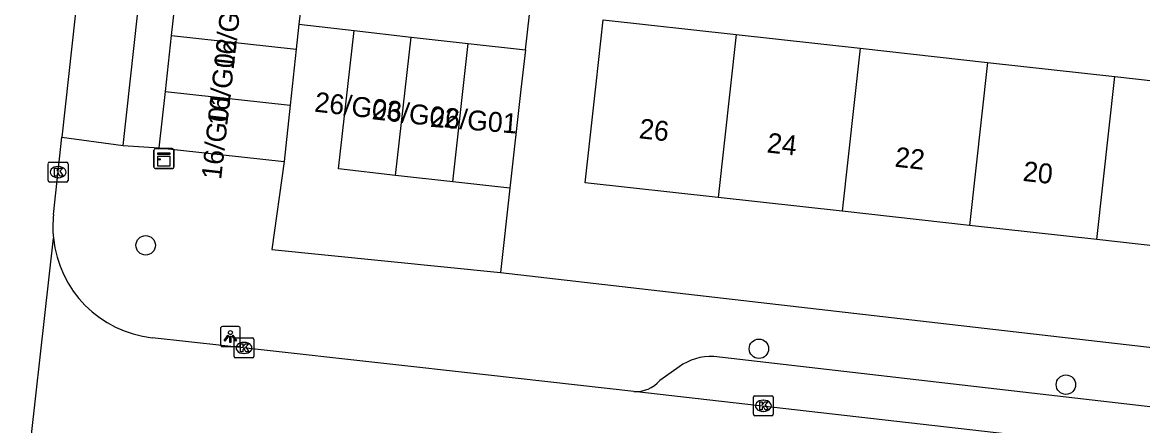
# Model space of a CAD drawing. Extents: x 161928 to 163055, y 386475 to 387428.
# Drawn here: x 162178.5 to 162234.9, y 387044.1 to 387064.4 of the extents above; entities that cross this region are included whole.
import ezdxf

# ---------------------------------------------------------------- set-up
doc = ezdxf.new("R2010")
doc.units = 0
for name, color, linetype in [('IMGEO_Boom', 7, 'Continuous'), ('IMGEO_Kast', 7, 'Continuous'), ('IMGEO_Kolk', 7, 'Continuous'), ('IMGEO_Lichtpunt', 7, 'Continuous'), ('IMGEO_Pand', 7, 'Continuous'), ('IMGEO_Pand_nummerreeks', 7, 'Continuous'), ('IMGEO_Rijbaan_lokaal_open', 7, 'Continuous'), ('IMGEO_Voetpad_open', 7, 'Continuous')]:
    doc.layers.add(name, color=color, linetype=linetype)

msp = doc.modelspace()

# ---------------------------------------------------------------- linework, layer by layer
at = {"layer": 'IMGEO_Boom'}
for centre in [(162184.742, 387053.165), (162215.596, 387047.966), (162231.042, 387046.162)]:
    msp.add_circle(centre, 0.489, dxfattribs=at)
at = {"layer": 'IMGEO_Kast'}
for p, q in [((162185.234, 387058.024), (162186.075, 387058.024)), ((162186.075, 387058.024), (162185.234, 387058.024)), ((162186.159, 387057.949), (162186.159, 387057.108)), ((162186.159, 387057.108), (162186.159, 387057.949)), ((162185.159, 387057.099), (162185.159, 387057.94)), ((162185.159, 387057.94), (162185.159, 387057.099)), ((162186.084, 387057.024), (162185.243, 387057.024)), ((162185.243, 387057.024), (162186.084, 387057.024))]:
    msp.add_line(p, q, dxfattribs=at)
for points in [[(162185.354, 387057.814), (162185.954, 387057.814), (162185.954, 387057.729), (162185.354, 387057.729), (162185.354, 387057.814)], [(162185.354, 387057.639), (162185.954, 387057.639), (162185.954, 387057.15), (162185.354, 387057.15), (162185.354, 387057.639)]]:
    msp.add_lwpolyline(points, dxfattribs=at)
msp.add_circle((162185.438, 387057.488), 0.0377, dxfattribs=at)
for centre, start, end in [((162185.237, 387057.946), 92.4484, 184.2845), ((162185.237, 387057.946), 92.4484, 184.2845), ((162186.081, 387057.946), 2.4484, 94.2845), ((162186.081, 387057.946), 2.4484, 94.2845), ((162185.237, 387057.102), 182.4484, 274.2845), ((162185.237, 387057.102), 182.4484, 274.2845), ((162186.081, 387057.102), 272.4484, 4.2845), ((162186.081, 387057.102), 272.4484, 4.2845)]:
    msp.add_arc(centre, 0.0779, start, end, dxfattribs=at)
at = {"layer": 'IMGEO_Kolk'}
for p, q in [((162179.837, 387056.416), (162179.837, 387057.268)), ((162179.912, 387057.342), (162180.764, 387057.342)), ((162180.325, 387057.122), (162180.35, 387057.122)), ((162180.838, 387057.268), (162180.838, 387056.416)), ((162180.764, 387056.342), (162179.912, 387056.342)), ((162180.348, 387056.562), (162180.323, 387056.562)), ((162189.187, 387047.583), (162189.187, 387048.435)), ((162189.262, 387048.509), (162190.114, 387048.509)), ((162190.188, 387048.435), (162190.188, 387047.583)), ((162189.675, 387048.289), (162189.7, 387048.289)), ((162190.114, 387047.509), (162189.262, 387047.509)), ((162189.698, 387047.729), (162189.673, 387047.729)), ((162215.394, 387045.601), (162216.246, 387045.601)), ((162215.319, 387044.675), (162215.319, 387045.527)), ((162215.807, 387045.381), (162215.832, 387045.381)), ((162216.32, 387045.527), (162216.32, 387044.675)), ((162216.246, 387044.601), (162215.394, 387044.601)), ((162215.83, 387044.821), (162215.805, 387044.821))]:
    msp.add_line(p, q, dxfattribs=at)
for points in [[(162179.837, 387056.416), (162179.837, 387057.268)], [(162179.912, 387057.342), (162180.764, 387057.342)], [(162180.158, 387057.042), (162180.281, 387057.042), (162180.281, 387056.891), (162180.411, 387057.042), (162180.575, 387057.042), (162180.429, 387056.891), (162180.582, 387056.642), (162180.43, 387056.642), (162180.345, 387056.806), (162180.281, 387056.739), (162180.281, 387056.642), (162180.158, 387056.642), (162180.158, 387057.042)], [(162180.838, 387057.268), (162180.838, 387056.416)], [(162180.764, 387056.342), (162179.912, 387056.342)], [(162189.187, 387047.583), (162189.187, 387048.435)], [(162189.262, 387048.509), (162190.114, 387048.509)], [(162190.188, 387048.435), (162190.188, 387047.583)], [(162189.508, 387048.209), (162189.631, 387048.209), (162189.631, 387048.058), (162189.761, 387048.209), (162189.925, 387048.209), (162189.779, 387048.058), (162189.932, 387047.809), (162189.78, 387047.809), (162189.695, 387047.973), (162189.631, 387047.906), (162189.631, 387047.809), (162189.508, 387047.809), (162189.508, 387048.209)], [(162190.114, 387047.509), (162189.262, 387047.509)], [(162215.394, 387045.601), (162216.246, 387045.601)], [(162215.319, 387044.675), (162215.319, 387045.527)], [(162215.64, 387045.301), (162215.763, 387045.301), (162215.763, 387045.15), (162215.893, 387045.301), (162216.057, 387045.301), (162215.911, 387045.15), (162216.064, 387044.901), (162215.912, 387044.901), (162215.827, 387045.065), (162215.763, 387044.998), (162215.763, 387044.901), (162215.64, 387044.901), (162215.64, 387045.301)], [(162216.32, 387045.527), (162216.32, 387044.675)], [(162216.246, 387044.601), (162215.394, 387044.601)]]:
    msp.add_lwpolyline(points, dxfattribs=at)
for centre, start, end in [((162179.914, 387057.266), 91.552, 178.448), ((162179.914, 387057.266), 91.552, 178.448), ((162180.762, 387057.266), 1.552, 88.448), ((162180.762, 387057.266), 1.552, 88.448), ((162179.914, 387056.418), 181.552, 268.448), ((162179.914, 387056.418), 181.552, 268.448), ((162180.762, 387056.418), 271.552, 358.448), ((162180.762, 387056.418), 271.552, 358.448), ((162189.264, 387048.433), 91.552, 178.448), ((162189.264, 387048.433), 91.552, 178.448), ((162190.112, 387048.433), 1.552, 88.448), ((162190.112, 387048.433), 1.552, 88.448), ((162189.264, 387047.585), 181.552, 268.448), ((162189.264, 387047.585), 181.552, 268.448), ((162190.112, 387047.585), 271.552, 358.448), ((162190.112, 387047.585), 271.552, 358.448), ((162215.396, 387045.525), 91.552, 178.448), ((162215.396, 387045.525), 91.552, 178.448), ((162216.244, 387045.525), 1.552, 88.448), ((162216.244, 387045.525), 1.552, 88.448), ((162215.396, 387044.677), 181.552, 268.448), ((162215.396, 387044.677), 181.552, 268.448), ((162216.244, 387044.677), 271.552, 358.448), ((162216.244, 387044.677), 271.552, 358.448)]:
    msp.add_arc(centre, 0.0765, start, end, dxfattribs=at)
for centre, major_axis, ratio, start_param, end_param in [((162180.324, 387056.842), (-0.387, 0.002), 0.722429, 4.712389, 7.853982), ((162180.349, 387056.842), (-0.39, 0.002), 0.717154, 1.570796, 4.712389), ((162189.674, 387048.009), (-0.387, 0.002), 0.722429, 4.712389, 7.853982), ((162189.699, 387048.009), (-0.39, 0.002), 0.717154, 1.570796, 4.712389), ((162215.806, 387045.101), (-0.387, 0.002), 0.722429, 4.712389, 7.853982), ((162215.831, 387045.101), (-0.39, 0.002), 0.717154, 1.570796, 4.712389)]:
    msp.add_ellipse(centre, major_axis=major_axis, ratio=ratio, start_param=start_param, end_param=end_param, dxfattribs=at)
at = {"layer": 'IMGEO_Lichtpunt'}
for p, q in [((162188.506, 387048.982), (162188.506, 387048.175)), ((162188.506, 387048.982), (162188.506, 387048.175)), ((162189.408, 387049.077), (162188.6, 387049.077)), ((162189.408, 387049.077), (162188.6, 387049.077)), ((162189.502, 387048.175), (162189.502, 387048.982)), ((162189.502, 387048.175), (162189.502, 387048.982)), ((162188.6, 387048.081), (162189.408, 387048.081)), ((162188.6, 387048.081), (162189.408, 387048.081))]:
    msp.add_line(p, q, dxfattribs=at)
for points in [[(162188.88, 387048.646), (162188.919, 387048.618), (162188.731, 387048.356), (162188.693, 387048.383), (162188.88, 387048.646)], [(162188.982, 387048.598), (162189.029, 387048.598), (162189.029, 387048.276), (162188.982, 387048.276), (162188.982, 387048.598)], [(162189.092, 387048.618), (162189.13, 387048.645), (162189.317, 387048.383), (162189.278, 387048.355), (162189.092, 387048.618)]]:
    msp.add_lwpolyline(points, dxfattribs=at)
msp.add_circle((162189.005, 387048.78), 0.0994, dxfattribs=at)
for centre, start, end in [((162188.6, 387048.982), 90, 180), ((162188.6, 387048.982), 90, 180), ((162189.408, 387048.982), 0, 90), ((162189.408, 387048.982), 0, 90), ((162188.6, 387048.175), 180, 270), ((162188.6, 387048.175), 180, 270), ((162189.408, 387048.175), 270, 0), ((162189.408, 387048.175), 270, 360)]:
    msp.add_arc(centre, 0.0946, start, end, dxfattribs=at)
at = {"layer": 'IMGEO_Pand'}
for points in [[(162203.848, 387062.981), (162205.287, 387075.728)], [(162186.043, 387063.707), (162186.351, 387066.527)], [(162192.624, 387065.842), (162192.452, 387064.271)], [(162192.452, 387064.271), (162192.316, 387063.022)], [(162192.452, 387064.271), (162195.226, 387063.957)], [(162213.546, 387055.569), (162206.856, 387056.312), (162207.408, 387061.282), (162207.765, 387064.503), (162214.456, 387063.76)], [(162185.735, 387060.888), (162186.043, 387063.707)], [(162186.043, 387063.707), (162192.316, 387063.022)], [(162197.315, 387056.68), (162194.441, 387057.004), (162195.226, 387063.957)], [(162195.226, 387063.957), (162198.1, 387063.632)], [(162197.315, 387056.68), (162198.1, 387063.632)], [(162198.1, 387063.632), (162200.973, 387063.306)], [(162214.456, 387063.76), (162213.546, 387055.569)], [(162214.456, 387063.76), (162220.693, 387063.068)], [(162192.316, 387063.022), (162192.008, 387060.202)], [(162200.189, 387056.355), (162200.973, 387063.306)], [(162200.973, 387063.306), (162203.848, 387062.981)], [(162220.693, 387063.068), (162219.784, 387054.877)], [(162220.693, 387063.068), (162227.101, 387062.356)], [(162203.848, 387062.981), (162203.624, 387061), (162203.063, 387056.031)], [(162227.101, 387062.356), (162226.191, 387054.165)], [(162227.101, 387062.356), (162233.511, 387061.644)], [(162232.602, 387053.453), (162233.511, 387061.644)], [(162233.511, 387061.644), (162239.898, 387060.935)], [(162185.427, 387058.068), (162185.735, 387060.888)], [(162185.735, 387060.888), (162192.008, 387060.202)], [(162192.008, 387060.202), (162191.701, 387057.384)], [(162185.427, 387058.068), (162191.701, 387057.384)], [(162200.189, 387056.355), (162197.315, 387056.68)], [(162203.063, 387056.031), (162200.189, 387056.355)], [(162219.784, 387054.877), (162213.546, 387055.569)], [(162226.191, 387054.165), (162219.784, 387054.877)], [(162232.602, 387053.453), (162226.191, 387054.165)], [(162238.988, 387052.744), (162232.602, 387053.453)]]:
    msp.add_lwpolyline(points, dxfattribs=at)
at = {"layer": 'IMGEO_Rijbaan_lokaal_open'}
for points in [[(162181.783, 387083.862), (162181.799, 387083.827), (162182.152, 387082.946), (162182.426, 387082.038), (162182.617, 387081.108), (162182.724, 387080.165), (162182.686, 387078.275), (162180.528, 387058.594)], [(162180.103, 387054.713), (162180.528, 387058.594)], [(162178.539, 387039.621), (162180.099, 387053.527)], [(162209.297, 387045.816), (162201.982, 387046.634), (162190.553, 387047.911), (162185.07, 387048.523)], [(162292.807, 387036.295), (162209.297, 387045.816)]]:
    msp.add_lwpolyline(points, dxfattribs=at)
for centre, radius, start, end in [((162185.757, 387054.101), 5.687, 173.8218, 185.7917), ((162185.682, 387054.102), 5.613, 185.883, 263.7379)]:
    msp.add_arc(centre, radius, start, end, dxfattribs=at)
at = {"layer": 'IMGEO_Voetpad_open'}
for points in [[(162183.617, 387058.182), (162185.796, 387078.002)], [(162180.528, 387058.594), (162183.617, 387058.182)], [(162183.617, 387058.182), (162185.427, 387058.068)], [(162191.701, 387057.384), (162191.095, 387052.958), (162202.596, 387051.794)], [(162203.063, 387056.031), (162202.596, 387051.794)], [(162202.596, 387051.794), (162288.423, 387041.928), (162292.928, 387041.432)], [(162289.168, 387038.822), (162288.165, 387038.944), (162213.325, 387047.577)], [(162211.581, 387047.056), (162210.611, 387046.365)]]:
    msp.add_lwpolyline(points, dxfattribs=at)
for centre, radius, start, end in [((162213.18, 387044.882), 2.699, 86.9298, 126.3361), ((162209.39, 387047.44), 1.627, 266.723, 318.6281)]:
    msp.add_arc(centre, radius, start, end, dxfattribs=at)

# ---------------------------------------------------------------- texts
at = {"layer": 'IMGEO_Pand_nummerreeks'}
for s, rotation, p in [('16/G03', 83.5645, (162189.16, 387061.962)), ('16/G02', 83.5645, (162188.841, 387059.137)), ('26/G03', 353.4181, (162193.201, 387059.888)), ('16/G01', 83.5645, (162188.536, 387056.434)), ('26/G02', 353.6598, (162196.097, 387059.504)), ('26/G01', 355.4747, (162199.034, 387059.124)), ('26', 353.6645, (162209.531, 387058.55)), ('24', 353.6645, (162215.967, 387057.835)), ('22', 353.6645, (162222.401, 387057.121)), ('20', 353.6645, (162228.843, 387056.406))]:
    msp.add_text(s, height=1, rotation=rotation, dxfattribs=at).set_placement(p)

doc.saveas('drawing.dxf')
